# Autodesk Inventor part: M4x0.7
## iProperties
IsCustomPart: 1
Created: 2015-10
Part Number: M4x0.7
Material: 강, 연강
Description: 6각머리 태핑 나사
Document SubType Name: Modeling
Standard: KS B 1003
Designer: mdu
Standards Organization: KS
Language: ko-KR
Size Designation: M 4 x 16
Categories: <MemberInstance><Categories><Category DisplayName="조임쇠" InternalName="e4da775c-781d-43d5-af7c-5136215cf5a6" Mnemonic="FSTN"><Category DisplayName="볼트" InternalN
Density: 1 g/cm^3
Author: mdu
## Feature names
1. Fillet2
